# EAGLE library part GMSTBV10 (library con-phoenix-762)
PHOENIX
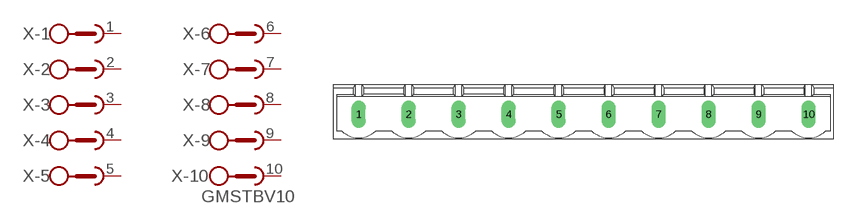
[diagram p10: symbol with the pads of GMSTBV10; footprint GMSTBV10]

Designator prefix X; gates -1=SKB -2=SKB -3=SKB -4=SKB -5=SKB -6=SKB -7=SKB -8=SKB -9=SKB -10=SKBV

## GMSTBV10 (MPN: GMSTBVA2,5/10-G-7,62; OC_FARNELL: 1793086; OC_NEWARK: 69R9519)  [GMSTBV10]
1  -1:1  pas
2  -2:1  pas
3  -3:1  pas
4  -4:1  pas
5  -5:1  pas
6  -6:1  pas
7  -7:1  pas
8  -8:1  pas
9  -9:1  pas
10  -10:1  pas

## Footprint GMSTBV10 (pad centres in mm)
PHOENIX
drill 1.397 long: 1 -34.29,0; 2 -26.67,0; 3 -19.05,0; 4 -11.43,0; 5 -3.81,0; 6 3.81,0; 7 11.43,0; 8 19.05,0; 9 26.67,0; 10 34.29,0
